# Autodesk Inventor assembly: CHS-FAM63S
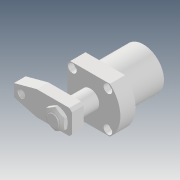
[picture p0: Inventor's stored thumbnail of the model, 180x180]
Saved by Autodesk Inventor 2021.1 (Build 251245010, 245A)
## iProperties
Created: 2019-05
Part Number: CHS-FAM63S
Description: STEP AP203
Document SubType Name: Assembly
Designer: user
Title: CHS-FAM63S.STEP
Revision Number: ÈÎºÎ
Sending System: SolidWorks 2017
Preprocessor: SwSTEP 2.0
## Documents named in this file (5)
- D:\Vault_2016\Projekty\Clamptek\Hydraulic\CHS\CHS-63\Inventor\CHS-FAM63S\CHS-FAM63S.iam
- D:\Vault_2016\Projekty\Clamptek\Hydraulic\CHS\CHS-63\Inventor\CHS-FAM63S\CHS-FAM63BT.ipt
- D:\Vault_2016\Projekty\Clamptek\Hydraulic\CHS\CHS-63\Inventor\CHS-FAM63S\M24.ipt
- D:\Vault_2016\Projekty\Clamptek\Hydraulic\CHS\CHS-63\Inventor\CHS-FAM63S\CHS-63S-01.ipt
- D:\Vault_2016\Projekty\Clamptek\Hydraulic\CHS\CHS-63\Inventor\CHS-FAM63S\CHS-63S-02.ipt
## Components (4 placed, 4 different names)
1. CHS-FAM63BT_1
2. M24_2
3. CHS-63S-01_3
4. CHS-63S-02_4
